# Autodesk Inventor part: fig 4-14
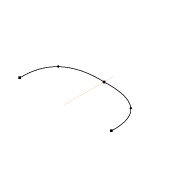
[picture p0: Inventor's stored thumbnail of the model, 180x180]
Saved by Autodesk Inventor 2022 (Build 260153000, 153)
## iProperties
Created: 2012-07
Part Number: fig 4-14
Material: Generic
Document SubType Name: Modeling
Designer: CADCIM
Density: 1 g/cm^3
Appearance: Default
Author: CADCIM
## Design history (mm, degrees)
sketch "Sketch1"
  geometry: L1 (-0.121, 16.232)-(-0.121, 0.498); 5 further points
  constraints: 2 end point, 2 symmetric about line, 1 vertical, 7 other
